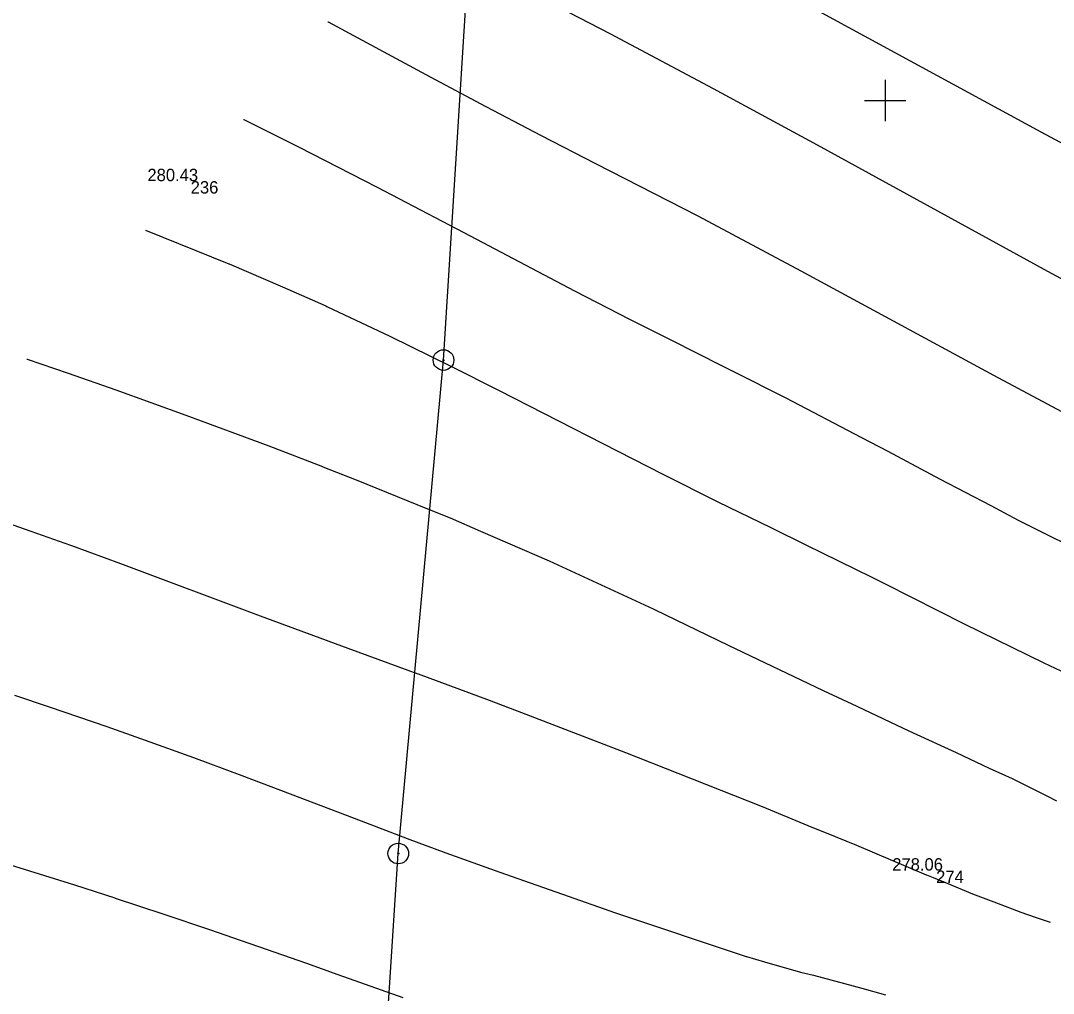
# Model space of a CAD drawing. Extents: x -771260 to -770828, y -1053564 to -1052811.
# Drawn here: x -771191.9 to -771141.9, y -1053143.2 to -1053096.1 of the extents above; entities that cross this region are included whole.
import ezdxf

# ---------------------------------------------------------------- set-up
doc = ezdxf.new("R2010")
doc.units = 0
for name, color, linetype in [('14_8_2023_krizky', 7, 'Continuous'), ('25_3_2019_krizky_JTSK', 7, 'Continuous'), ('25_3_2019_vrstevnice_interval_po_1m', 7, 'Continuous'), ('25_3_2019_zamereny_bod', 7, 'Continuous'), ('25_3_2019_zamereny_bod_cislo', 7, 'Continuous'), ('25_3_2019_zamereny_bod_vyska', 7, 'Continuous'), ('Default', 7, 'Continuous'), ('DKM_Hranice parcel', 7, 'Continuous'), ('DKM_Značky bodu BP', 7, 'Continuous')]:
    doc.layers.add(name, color=color, linetype=linetype)

# ---------------------------------------------------------------- blocks, each defined once
blk = doc.blocks.new('POINT_DISPLAY')
at = {"layer": 'Default'}
blk.add_line((0, 0), (0, 0), dxfattribs=at)
blk = doc.blocks.new('KRIZEK')
at = {"layer": '25_3_2019_krizky_JTSK'}
for p, q in [((0, 10), (0, -10)), ((-10, 0), (10, 0))]:
    blk.add_line(p, q, dxfattribs=at)

msp = doc.modelspace()

# ---------------------------------------------------------------- linework, layer by layer
at = {"layer": '25_3_2019_vrstevnice_interval_po_1m'}
for points in [[(-771168.776, -1053087.342), (-771168.763, -1053087.349), (-771165.344, -1053089.131), (-771160.566, -1053091.665), (-771160.484, -1053091.709), (-771154.54, -1053094.928), (-771142.457, -1053101.522), (-771137.451, -1053104.205), (-771135.684, -1053105.13), (-771131.859, -1053107.066), (-771131.854, -1053107.069), (-771131.434, -1053107.274), (-771130.765, -1053107.58), (-771129.688, -1053108.126), (-771128.779, -1053108.661), (-771128.775, -1053108.663), (-771128.055, -1053109.142), (-771126.81, -1053110), (-771125.868, -1053110.595), (-771124.886, -1053111.103), (-771123.868, -1053111.535), (-771123.338, -1053111.71), (-771122.796, -1053111.853), (-771121.671, -1053112.059)], [(-771168.295, -1053094.166), (-771163.323, -1053096.749), (-771158.324, -1053099.418), (-771153.294, -1053102.153), (-771142.139, -1053108.267), (-771138.362, -1053110.296), (-771134.534, -1053112.226), (-771134.529, -1053112.228), (-771133.439, -1053112.738), (-771132.353, -1053113.267), (-771131.275, -1053113.81), (-771130.801, -1053114.063), (-771130.218, -1053114.395), (-771129.158, -1053115.022), (-771129.154, -1053115.024), (-771128.433, -1053115.484), (-771128.238, -1053115.616), (-771127.293, -1053116.204), (-771126.261, -1053116.764), (-771125.307, -1053117.175), (-771124.249, -1053117.524), (-771124.245, -1053117.525), (-771123.66, -1053117.673), (-771123.156, -1053117.784)], [(-771176.978, -1053096.183), (-771176.978, -1053096.183)], [(-771176.978, -1053096.183), (-771176.968, -1053096.188), (-771172.03, -1053098.849), (-771169.337, -1053100.284), (-771166.658, -1053101.691), (-771164.02, -1053103.044), (-771159.068, -1053105.585), (-771154.074, -1053108.244), (-771144.754, -1053113.309), (-771140.971, -1053115.327)], [(-771163.323, -1053096.749), (-771163.323, -1053096.749)], [(-771172.03, -1053098.849), (-771172.03, -1053098.849)], [(-771158.324, -1053099.418), (-771158.324, -1053099.418)], [(-771169.337, -1053100.284), (-771169.337, -1053100.284)], [(-771181.062, -1053100.923), (-771181.062, -1053100.923)], [(-771181.062, -1053100.923), (-771181.053, -1053100.928), (-771178.401, -1053102.243), (-771174.597, -1053104.195), (-771170.399, -1053106.392), (-771165.037, -1053109.214), (-771162.372, -1053110.592), (-771159.755, -1053111.901), (-771159.735, -1053111.911), (-771154.83, -1053114.386), (-771151.146, -1053116.324), (-771149.862, -1053116.99), (-771147.357, -1053118.33), (-771144.881, -1053119.623), (-771143.561, -1053120.322), (-771139.721, -1053122.231)], [(-771166.658, -1053101.691), (-771166.658, -1053101.691)], [(-771142.457, -1053101.522), (-771142.457, -1053101.522)], [(-771178.401, -1053102.243), (-771178.401, -1053102.243)], [(-771153.294, -1053102.153), (-771153.294, -1053102.153)], [(-771174.597, -1053104.195), (-771174.597, -1053104.195)], [(-771159.068, -1053105.585), (-771159.068, -1053105.585)], [(-771185.816, -1053106.281), (-771185.816, -1053106.281)], [(-771185.816, -1053106.281), (-771185.806, -1053106.285), (-771181.773, -1053107.911), (-771181.755, -1053107.919), (-771179.174, -1053109.027), (-771177.084, -1053109.953), (-771177.03, -1053109.977), (-771173.981, -1053111.422), (-771170.993, -1053112.884), (-771168.723, -1053114.028), (-771160.758, -1053118.098), (-771158.099, -1053119.44), (-771155.525, -1053120.685), (-771155.505, -1053120.695), (-771153.84, -1053121.521), (-771150.644, -1053123.079), (-771149.994, -1053123.416), (-771146.168, -1053125.352), (-771142.315, -1053127.234), (-771142.31, -1053127.236), (-771141.221, -1053127.747)], [(-771170.399, -1053106.392), (-771170.399, -1053106.392)], [(-771181.755, -1053107.919), (-771181.755, -1053107.919)], [(-771154.074, -1053108.244), (-771154.074, -1053108.244)], [(-771142.139, -1053108.267), (-771142.139, -1053108.267)], [(-771179.174, -1053109.027), (-771179.174, -1053109.027)], [(-771165.037, -1053109.214), (-771165.037, -1053109.214)], [(-771177.03, -1053109.977), (-771177.03, -1053109.977)], [(-771162.372, -1053110.592), (-771162.372, -1053110.592)], [(-771173.981, -1053111.422), (-771173.981, -1053111.422)], [(-771159.735, -1053111.911), (-771159.735, -1053111.911)], [(-771191.556, -1053112.527), (-771191.556, -1053112.527)], [(-771191.556, -1053112.527), (-771191.545, -1053112.531), (-771189.561, -1053113.205), (-771187.243, -1053114.015), (-771183.856, -1053115.234), (-771179.839, -1053116.729), (-771177.246, -1053117.729), (-771177.228, -1053117.736), (-771175.613, -1053118.368), (-771172.151, -1053119.77), (-771171.06, -1053120.22), (-771169.582, -1053120.851), (-771166.268, -1053122.292), (-771161.221, -1053124.627), (-771161.165, -1053124.653), (-771157.597, -1053126.385), (-771153, -1053128.577), (-771151.36, -1053129.333), (-771151.341, -1053129.342), (-771148.852, -1053130.527), (-771146.552, -1053131.575), (-771144.961, -1053132.337), (-771144.956, -1053132.339), (-771143.849, -1053132.839), (-771142.778, -1053133.374), (-771142.193, -1053133.657), (-771141.696, -1053133.911)], [(-771189.561, -1053113.205), (-771189.561, -1053113.205)], [(-771170.993, -1053112.884), (-771170.993, -1053112.884)], [(-771144.754, -1053113.309), (-771144.754, -1053113.309)], [(-771187.243, -1053114.015), (-771187.243, -1053114.015)], [(-771168.723, -1053114.028), (-771168.723, -1053114.028)], [(-771154.83, -1053114.386), (-771154.83, -1053114.386)], [(-771183.856, -1053115.234), (-771183.856, -1053115.234)], [(-771179.839, -1053116.729), (-771179.839, -1053116.729)], [(-771151.146, -1053116.324), (-771151.146, -1053116.324)], [(-771149.862, -1053116.99), (-771149.862, -1053116.99)], [(-771177.228, -1053117.736), (-771177.228, -1053117.736)], [(-771160.758, -1053118.098), (-771160.758, -1053118.098)], [(-771175.613, -1053118.368), (-771175.613, -1053118.368)], [(-771147.357, -1053118.33), (-771147.357, -1053118.33)], [(-771172.151, -1053119.77), (-771172.151, -1053119.77)], [(-771158.099, -1053119.44), (-771158.099, -1053119.44)], [(-771144.881, -1053119.623), (-771144.881, -1053119.623)], [(-771193.676, -1053120.05), (-771191.356, -1053120.854), (-771189.438, -1053121.543), (-771189.393, -1053121.559), (-771187.013, -1053122.432), (-771180.256, -1053124.956), (-771176.015, -1053126.523), (-771172.618, -1053127.764), (-771172.6, -1053127.771), (-771169.174, -1053129.044), (-771167.598, -1053129.641), (-771162.566, -1053131.577), (-771160.038, -1053132.572), (-771155.955, -1053134.193), (-771153.734, -1053135.118), (-771152.414, -1053135.639), (-771151.387, -1053136.058), (-771148.015, -1053137.499), (-771147.993, -1053137.508), (-771147.665, -1053137.636), (-771147.279, -1053137.787), (-771147.259, -1053137.795), (-771145.77, -1053138.421), (-771144.599, -1053138.858), (-771143.422, -1053139.311), (-771142.729, -1053139.554), (-771142.004, -1053139.792)], [(-771171.06, -1053120.22), (-771171.06, -1053120.22)], [(-771155.505, -1053120.695), (-771155.505, -1053120.695)], [(-771143.561, -1053120.322), (-771143.561, -1053120.322)], [(-771191.356, -1053120.854), (-771191.356, -1053120.854)], [(-771169.582, -1053120.851), (-771169.582, -1053120.851)], [(-771189.393, -1053121.559), (-771189.393, -1053121.559)], [(-771153.84, -1053121.521), (-771153.84, -1053121.521)], [(-771187.013, -1053122.432), (-771187.013, -1053122.432)], [(-771166.268, -1053122.292), (-771166.268, -1053122.292)], [(-771150.644, -1053123.079), (-771150.644, -1053123.079)], [(-771149.994, -1053123.416), (-771149.994, -1053123.416)], [(-771161.165, -1053124.653), (-771161.165, -1053124.653)], [(-771180.256, -1053124.956), (-771180.256, -1053124.956)], [(-771146.168, -1053125.352), (-771146.168, -1053125.352)], [(-771176.015, -1053126.523), (-771176.015, -1053126.523)], [(-771157.597, -1053126.385), (-771157.597, -1053126.385)], [(-771142.315, -1053127.234), (-771142.315, -1053127.234)], [(-771172.6, -1053127.771), (-771172.6, -1053127.771)], [(-771153, -1053128.577), (-771153, -1053128.577)], [(-771192.153, -1053128.801), (-771190.481, -1053129.358), (-771190.467, -1053129.363), (-771187.689, -1053130.323), (-771185.825, -1053130.976), (-771183.491, -1053131.821), (-771181.149, -1053132.689), (-771178.799, -1053133.581), (-771175.363, -1053134.893), (-771173.131, -1053135.746), (-771171.268, -1053136.436), (-771168.873, -1053137.294), (-771168.098, -1053137.565), (-771165.613, -1053138.433), (-771163.05, -1053139.348), (-771156.732, -1053141.457), (-771156.706, -1053141.464), (-771155.829, -1053141.708), (-771154.087, -1053142.209), (-771153.47, -1053142.361), (-771151.125, -1053142.985), (-771149.981, -1053143.315)], [(-771169.174, -1053129.044), (-771169.174, -1053129.044)], [(-771190.467, -1053129.363), (-771190.467, -1053129.363)], [(-771167.598, -1053129.641), (-771167.598, -1053129.641)], [(-771151.341, -1053129.342), (-771151.341, -1053129.342)], [(-771187.689, -1053130.323), (-771187.689, -1053130.323)], [(-771148.852, -1053130.527), (-771148.852, -1053130.527)], [(-771185.825, -1053130.976), (-771185.825, -1053130.976)], [(-771162.566, -1053131.577), (-771162.566, -1053131.577)], [(-771146.552, -1053131.575), (-771146.552, -1053131.575)], [(-771209.642, -1053132.099), (-771209.629, -1053132.101), (-771208.51, -1053132.352), (-771207.02, -1053132.719), (-771207.009, -1053132.722), (-771204.903, -1053133.3), (-771203.924, -1053133.589), (-771203.883, -1053133.601), (-771201.909, -1053134.161), (-771197.052, -1053135.594), (-771193.152, -1053136.774), (-771189.24, -1053137.991), (-771187.288, -1053138.622), (-771187.274, -1053138.627), (-771184.971, -1053139.384), (-771182.658, -1053140.168), (-771181.591, -1053140.542), (-771180.339, -1053140.968), (-771178.014, -1053141.786), (-771176.495, -1053142.335), (-771173.356, -1053143.447)], [(-771183.491, -1053131.821), (-771183.491, -1053131.821)], [(-771181.149, -1053132.689), (-771181.149, -1053132.689)], [(-771160.038, -1053132.572), (-771160.038, -1053132.572)], [(-771144.961, -1053132.337), (-771144.961, -1053132.337)], [(-771143.849, -1053132.839), (-771143.849, -1053132.839)], [(-771178.799, -1053133.581), (-771178.799, -1053133.581)], [(-771142.778, -1053133.374), (-771142.778, -1053133.374)], [(-771142.193, -1053133.657), (-771142.193, -1053133.657)], [(-771155.955, -1053134.193), (-771155.955, -1053134.193)], [(-771153.734, -1053135.118), (-771153.734, -1053135.118)], [(-771173.131, -1053135.746), (-771173.131, -1053135.746)], [(-771152.414, -1053135.639), (-771152.414, -1053135.639)], [(-771151.387, -1053136.058), (-771151.387, -1053136.058)], [(-771171.268, -1053136.436), (-771171.268, -1053136.436)], [(-771168.873, -1053137.294), (-771168.873, -1053137.294)], [(-771148.015, -1053137.499), (-771148.015, -1053137.499)], [(-771189.24, -1053137.991), (-771189.24, -1053137.991)], [(-771147.259, -1053137.795), (-771147.259, -1053137.795)], [(-771187.274, -1053138.627), (-771187.274, -1053138.627)], [(-771165.613, -1053138.433), (-771165.613, -1053138.433)], [(-771145.77, -1053138.421), (-771145.77, -1053138.421)], [(-771144.599, -1053138.858), (-771144.599, -1053138.858)], [(-771184.971, -1053139.384), (-771184.971, -1053139.384)], [(-771163.05, -1053139.348), (-771163.05, -1053139.348)], [(-771143.422, -1053139.311), (-771143.422, -1053139.311)], [(-771142.729, -1053139.554), (-771142.729, -1053139.554)], [(-771182.658, -1053140.168), (-771182.658, -1053140.168)], [(-771181.591, -1053140.542), (-771181.591, -1053140.542)], [(-771180.339, -1053140.968), (-771180.339, -1053140.968)], [(-771156.732, -1053141.457), (-771156.732, -1053141.457)], [(-771155.829, -1053141.708), (-771155.829, -1053141.708)], [(-771178.014, -1053141.786), (-771178.014, -1053141.786)], [(-771154.087, -1053142.209), (-771154.087, -1053142.209)], [(-771176.495, -1053142.335), (-771176.495, -1053142.335)], [(-771153.47, -1053142.361), (-771153.47, -1053142.361)], [(-771151.125, -1053142.985), (-771151.125, -1053142.985)]]:
    msp.add_lwpolyline(points, dxfattribs=at)
at = {"layer": 'DKM_Hranice parcel'}
msp.add_lwpolyline([(-771234.22, -1053144), (-771211.57, -1053140.91), (-771205.43, -1053140.71), (-771198.42, -1053142.38), (-771188.44, -1053147.21), (-771182.18, -1053149.49), (-771178.16, -1053150.12), (-771175.05, -1053149.44), (-771174.13, -1053144.96), (-771173.57, -1053136.47), (-771171.38, -1053112.57), (-771169.97, -1053090.2), (-771169.61, -1053079.22)], dxfattribs=at)
at = {"layer": 'DKM_Značky bodu BP'}
for centre, radius in [((-771171.38, -1053112.57), 0.5), ((-771171.38, -1053112.57), 0.0303), ((-771173.57, -1053136.47), 0.5), ((-771173.57, -1053136.47), 0.0303)]:
    msp.add_circle(centre, radius, dxfattribs=at)

# ---------------------------------------------------------------- block references
at = {"layer": '14_8_2023_krizky', "xscale": 0.1, "yscale": 0.10000000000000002}
msp.add_blockref('KRIZEK', (-771150, -1053100), dxfattribs=at)
at = {"layer": '25_3_2019_zamereny_bod', "xscale": 0.1, "yscale": 0.10000000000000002}
for p in [(-771183.62, -1053103.907), (-771147.526, -1053137.296)]:
    msp.add_blockref('POINT_DISPLAY', p, dxfattribs=at)

# ---------------------------------------------------------------- texts
at = {"layer": '25_3_2019_zamereny_bod_cislo'}
for s, p in [('236', (-771183.62, -1053104.507)), ('274', (-771147.526, -1053137.896))]:
    msp.add_text(s, height=0.6, dxfattribs=at).set_placement(p)
at = {"layer": '25_3_2019_zamereny_bod_vyska'}
for s, p in [('280.43 ', (-771185.716, -1053103.907)), ('278.06 ', (-771149.65, -1053137.296))]:
    msp.add_text(s, height=0.6, dxfattribs=at).set_placement(p)

doc.saveas('drawing.dxf')
